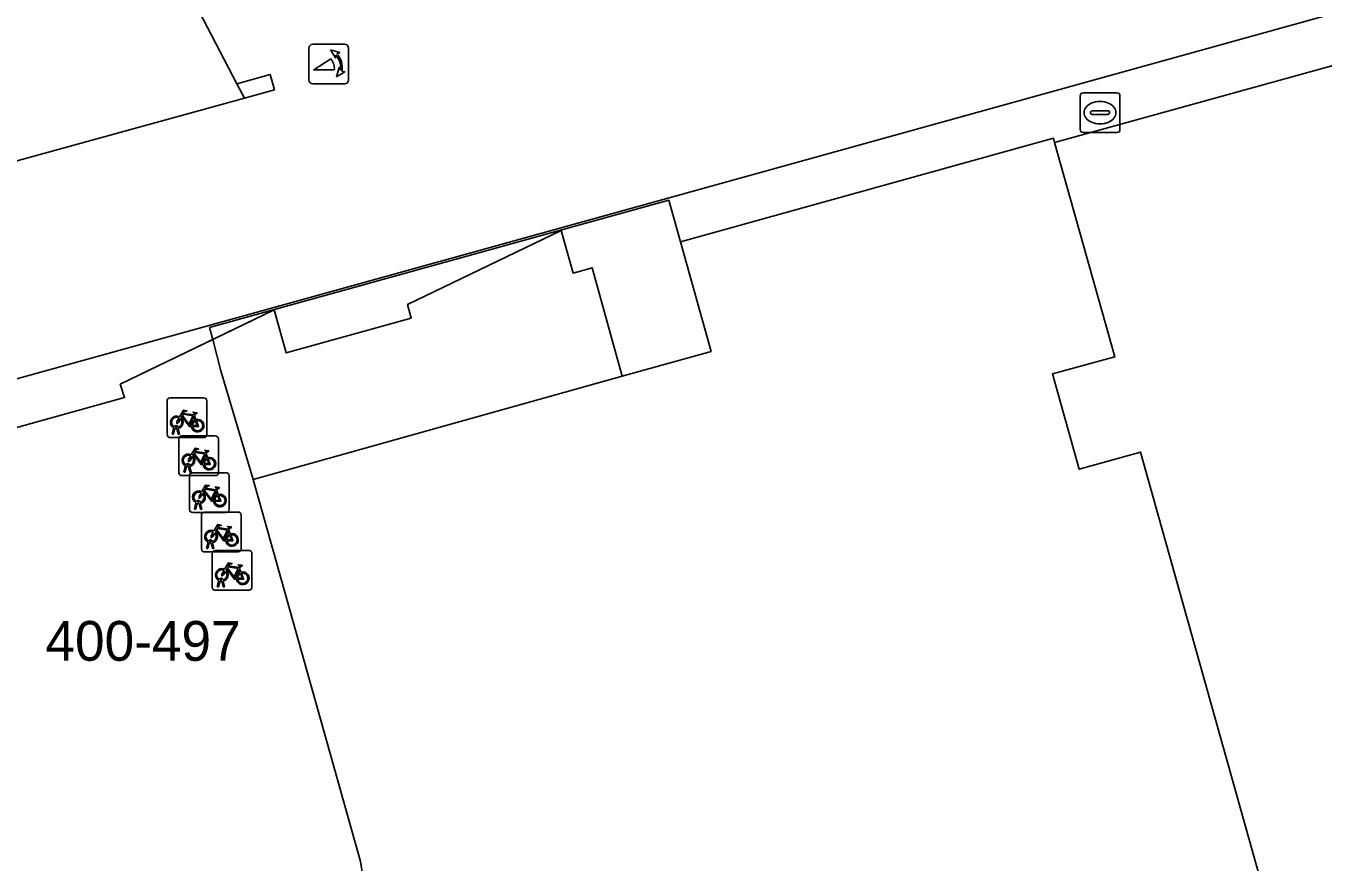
# Model space of a CAD drawing. Extents: x 159053 to 160042, y 380449 to 381423.
# Drawn here: x 159209.05 to 159241.67, y 381114.07 to 381135.09 of the extents above; entities that cross this region are included whole.
import ezdxf

# ---------------------------------------------------------------- set-up
doc = ezdxf.new("R2010")
doc.units = 0
for name, color, linetype in [('IMGEO_Fietsenrek', 7, 'Continuous'), ('IMGEO_Groenvoorziening', 7, 'Continuous'), ('IMGEO_Kolk', 7, 'Continuous'), ('IMGEO_Muur', 7, 'Continuous'), ('IMGEO_Pand', 7, 'Continuous'), ('IMGEO_Pand_nummerreeks', 7, 'Continuous'), ('IMGEO_Pand_overbouw', 7, 'Continuous'), ('IMGEO_Pand_vergunning_verleend', 7, 'Continuous'), ('IMGEO_Poller', 7, 'Continuous'), ('IMGEO_Rijbaan_lokaal_open', 7, 'Continuous'), ('IMGEO_Voetpad_open', 7, 'Continuous')]:
    doc.layers.add(name, color=color, linetype=linetype)

msp = doc.modelspace()

# ---------------------------------------------------------------- linework, layer by layer
at = {"layer": 'IMGEO_Fietsenrek'}
for p, q in [((159212.605, 381124.816), (159212.605, 381125.657)), ((159212.605, 381125.657), (159212.605, 381124.816)), ((159212.68, 381125.741), (159213.521, 381125.741)), ((159213.521, 381125.741), (159212.68, 381125.741)), ((159213.605, 381125.666), (159213.605, 381124.825)), ((159213.605, 381124.825), (159213.605, 381125.666)), ((159213.292, 381125.29), (159213.328, 381125.195)), ((159212.732, 381124.825), (159212.771, 381124.985)), ((159212.801, 381124.973), (159212.766, 381124.825)), ((159212.843, 381124.997), (159212.842, 381125.001)), ((159212.884, 381124.825), (159212.85, 381124.967)), ((159212.874, 381125.008), (159212.875, 381125.001)), ((159212.882, 381124.971), (159212.917, 381124.825)), ((159213.53, 381124.741), (159212.689, 381124.741)), ((159212.689, 381124.741), (159213.53, 381124.741)), ((159212.766, 381124.825), (159212.732, 381124.825)), ((159212.917, 381124.825), (159212.884, 381124.825)), ((159212.899, 381123.86), (159212.899, 381124.701)), ((159212.899, 381124.701), (159212.899, 381123.86)), ((159212.974, 381124.785), (159213.815, 381124.785)), ((159213.815, 381124.785), (159212.974, 381124.785)), ((159213.899, 381124.71), (159213.899, 381123.869)), ((159213.899, 381123.869), (159213.899, 381124.71)), ((159213.586, 381124.334), (159213.622, 381124.239)), ((159213.026, 381123.869), (159213.065, 381124.029)), ((159213.095, 381124.017), (159213.06, 381123.869)), ((159213.137, 381124.041), (159213.136, 381124.045)), ((159213.178, 381123.869), (159213.144, 381124.011)), ((159213.168, 381124.052), (159213.169, 381124.045)), ((159213.176, 381124.015), (159213.211, 381123.869)), ((159213.824, 381123.785), (159212.983, 381123.785)), ((159212.983, 381123.785), (159213.824, 381123.785)), ((159213.06, 381123.869), (159213.026, 381123.869)), ((159213.164, 381122.934), (159213.164, 381123.775)), ((159213.164, 381123.775), (159213.164, 381122.934)), ((159213.211, 381123.869), (159213.178, 381123.869)), ((159213.239, 381123.859), (159214.08, 381123.859)), ((159214.08, 381123.859), (159213.239, 381123.859)), ((159214.164, 381123.784), (159214.164, 381122.943)), ((159214.164, 381122.943), (159214.164, 381123.784)), ((159213.851, 381123.408), (159213.887, 381123.313)), ((159213.291, 381122.943), (159213.33, 381123.103)), ((159213.36, 381123.091), (159213.325, 381122.943)), ((159213.402, 381123.115), (159213.401, 381123.119)), ((159213.443, 381122.943), (159213.409, 381123.085)), ((159213.433, 381123.126), (159213.434, 381123.119)), ((159213.441, 381123.089), (159213.476, 381122.943)), ((159214.089, 381122.859), (159213.248, 381122.859)), ((159213.248, 381122.859), (159214.089, 381122.859)), ((159213.325, 381122.943), (159213.291, 381122.943)), ((159213.476, 381122.943), (159213.443, 381122.943)), ((159213.468, 381121.943), (159213.468, 381122.784)), ((159213.468, 381122.784), (159213.468, 381121.943)), ((159213.543, 381122.868), (159214.384, 381122.868)), ((159214.384, 381122.868), (159213.543, 381122.868)), ((159214.468, 381122.793), (159214.468, 381121.952)), ((159214.468, 381121.952), (159214.468, 381122.793)), ((159214.155, 381122.417), (159214.191, 381122.322)), ((159213.595, 381121.952), (159213.634, 381122.112)), ((159213.664, 381122.1), (159213.629, 381121.952)), ((159213.706, 381122.124), (159213.705, 381122.128)), ((159213.747, 381121.952), (159213.713, 381122.094)), ((159213.737, 381122.135), (159213.738, 381122.128)), ((159213.745, 381122.098), (159213.78, 381121.952)), ((159214.393, 381121.868), (159213.552, 381121.868)), ((159213.552, 381121.868), (159214.393, 381121.868)), ((159213.629, 381121.952), (159213.595, 381121.952)), ((159213.738, 381120.98), (159213.738, 381121.821)), ((159213.738, 381121.821), (159213.738, 381120.98)), ((159213.78, 381121.952), (159213.747, 381121.952)), ((159213.813, 381121.905), (159214.654, 381121.905)), ((159214.654, 381121.905), (159213.813, 381121.905)), ((159214.738, 381121.83), (159214.738, 381120.989)), ((159214.738, 381120.989), (159214.738, 381121.83)), ((159214.425, 381121.454), (159214.461, 381121.359)), ((159213.865, 381120.989), (159213.904, 381121.149)), ((159213.934, 381121.137), (159213.899, 381120.989)), ((159213.976, 381121.161), (159213.975, 381121.165)), ((159214.017, 381120.989), (159213.983, 381121.131)), ((159214.007, 381121.172), (159214.008, 381121.165)), ((159214.015, 381121.135), (159214.05, 381120.989)), ((159214.663, 381120.905), (159213.822, 381120.905)), ((159213.822, 381120.905), (159214.663, 381120.905)), ((159213.899, 381120.989), (159213.865, 381120.989)), ((159214.05, 381120.989), (159214.017, 381120.989))]:
    msp.add_line(p, q, dxfattribs=at)
for points in [[(159212.918, 381125.267), (159213.013, 381125.431), (159213.099, 381125.417), (159213.101, 381125.408), (159213.045, 381125.397), (159213.018, 381125.352), (159213.274, 381125.311)], [(159213.261, 381125.286), (159213.004, 381125.327), (159212.987, 381125.298), (159213.154, 381125.078), (159213.261, 381125.286)], [(159213.274, 381125.311), (159213.299, 381125.36), (159213.293, 381125.364), (159213.27, 381125.368), (159213.258, 381125.375), (159213.257, 381125.378), (159213.259, 381125.383), (159213.354, 381125.368), (159213.356, 381125.358), (159213.346, 381125.345), (159213.334, 381125.339), (159213.32, 381125.345), (159213.292, 381125.29)], [(159212.939, 381125.215), (159212.887, 381125.125), (159212.847, 381125.1), (159212.848, 381125.147), (159212.903, 381125.241)], [(159213.214, 381125.023), (159213.164, 381125.023), (159212.973, 381125.274), (159212.954, 381125.242)], [(159213.309, 381125.188), (159213.279, 381125.265), (159213.17, 381125.047), (159213.213, 381125.047)], [(159213.243, 381125.047), (159213.363, 381125.046), (159213.319, 381125.16)], [(159213.339, 381125.167), (159213.394, 381125.022), (159213.244, 381125.022)], [(159213.212, 381124.311), (159213.307, 381124.475), (159213.393, 381124.461), (159213.395, 381124.452), (159213.339, 381124.441), (159213.312, 381124.396), (159213.568, 381124.355)], [(159213.508, 381124.067), (159213.458, 381124.067), (159213.267, 381124.318), (159213.248, 381124.286)], [(159213.555, 381124.33), (159213.298, 381124.371), (159213.281, 381124.342), (159213.448, 381124.122), (159213.555, 381124.33)], [(159213.603, 381124.232), (159213.573, 381124.309), (159213.464, 381124.091), (159213.507, 381124.091)], [(159213.568, 381124.355), (159213.593, 381124.404), (159213.587, 381124.408), (159213.564, 381124.412), (159213.552, 381124.419), (159213.551, 381124.422), (159213.553, 381124.427), (159213.648, 381124.412), (159213.65, 381124.402), (159213.64, 381124.389), (159213.628, 381124.383), (159213.614, 381124.389), (159213.586, 381124.334)], [(159213.233, 381124.259), (159213.181, 381124.169), (159213.141, 381124.144), (159213.142, 381124.191), (159213.197, 381124.285)], [(159213.537, 381124.091), (159213.657, 381124.09), (159213.613, 381124.204)], [(159213.633, 381124.211), (159213.688, 381124.066), (159213.538, 381124.066)], [(159213.498, 381123.333), (159213.446, 381123.243), (159213.406, 381123.218), (159213.407, 381123.265), (159213.462, 381123.359)], [(159213.477, 381123.385), (159213.572, 381123.549), (159213.658, 381123.535), (159213.66, 381123.526), (159213.604, 381123.515), (159213.577, 381123.47), (159213.833, 381123.429)], [(159213.773, 381123.141), (159213.723, 381123.141), (159213.532, 381123.392), (159213.513, 381123.36)], [(159213.82, 381123.404), (159213.563, 381123.445), (159213.546, 381123.416), (159213.713, 381123.196), (159213.82, 381123.404)], [(159213.868, 381123.306), (159213.838, 381123.383), (159213.729, 381123.165), (159213.772, 381123.165)], [(159213.833, 381123.429), (159213.858, 381123.478), (159213.852, 381123.482), (159213.829, 381123.486), (159213.817, 381123.493), (159213.816, 381123.496), (159213.818, 381123.501), (159213.913, 381123.486), (159213.915, 381123.476), (159213.905, 381123.463), (159213.893, 381123.457), (159213.879, 381123.463), (159213.851, 381123.408)], [(159213.802, 381123.165), (159213.922, 381123.164), (159213.878, 381123.278)], [(159213.898, 381123.285), (159213.953, 381123.14), (159213.803, 381123.14)], [(159213.802, 381122.342), (159213.75, 381122.252), (159213.71, 381122.227), (159213.711, 381122.274), (159213.766, 381122.368)], [(159213.781, 381122.394), (159213.876, 381122.558), (159213.962, 381122.544), (159213.964, 381122.535), (159213.908, 381122.524), (159213.881, 381122.479), (159214.137, 381122.438)], [(159214.077, 381122.15), (159214.027, 381122.15), (159213.836, 381122.401), (159213.817, 381122.369)], [(159214.124, 381122.413), (159213.867, 381122.454), (159213.85, 381122.425), (159214.017, 381122.205), (159214.124, 381122.413)], [(159214.172, 381122.315), (159214.142, 381122.392), (159214.033, 381122.174), (159214.076, 381122.174)], [(159214.137, 381122.438), (159214.162, 381122.487), (159214.156, 381122.491), (159214.133, 381122.495), (159214.121, 381122.502), (159214.12, 381122.505), (159214.122, 381122.51), (159214.217, 381122.495), (159214.219, 381122.485), (159214.209, 381122.472), (159214.197, 381122.466), (159214.183, 381122.472), (159214.155, 381122.417)], [(159214.106, 381122.174), (159214.226, 381122.173), (159214.182, 381122.287)], [(159214.202, 381122.294), (159214.257, 381122.149), (159214.107, 381122.149)], [(159214.072, 381121.379), (159214.02, 381121.289), (159213.98, 381121.264), (159213.981, 381121.311), (159214.036, 381121.405)], [(159214.051, 381121.431), (159214.146, 381121.595), (159214.232, 381121.581), (159214.234, 381121.572), (159214.178, 381121.561), (159214.151, 381121.516), (159214.407, 381121.475)], [(159214.347, 381121.187), (159214.297, 381121.187), (159214.106, 381121.438), (159214.087, 381121.406)], [(159214.394, 381121.45), (159214.137, 381121.491), (159214.12, 381121.462), (159214.287, 381121.242), (159214.394, 381121.45)], [(159214.442, 381121.352), (159214.412, 381121.429), (159214.303, 381121.211), (159214.346, 381121.211)], [(159214.407, 381121.475), (159214.432, 381121.524), (159214.426, 381121.528), (159214.403, 381121.532), (159214.391, 381121.539), (159214.39, 381121.542), (159214.392, 381121.547), (159214.487, 381121.532), (159214.489, 381121.522), (159214.479, 381121.509), (159214.467, 381121.503), (159214.453, 381121.509), (159214.425, 381121.454)], [(159214.376, 381121.211), (159214.496, 381121.21), (159214.452, 381121.324)], [(159214.472, 381121.331), (159214.527, 381121.186), (159214.377, 381121.186)]]:
    msp.add_lwpolyline(points, dxfattribs=at)
for centre, radius, start, end in [((159212.683, 381125.663), 0.0779, 92.4484, 184.2845), ((159212.683, 381125.663), 0.0779, 92.4484, 184.2845), ((159213.527, 381125.663), 0.0779, 2.4484, 94.2845), ((159213.527, 381125.663), 0.0779, 2.4484, 94.2845), ((159212.845, 381125.126), 0.159, 62.6766, 242.1369), ((159212.845, 381125.126), 0.129, 63.3192, 238.903), ((159212.825, 381124.997), 0.0499, 12.8025, 158.6934), ((159212.845, 381125.126), 0.159, 253.9967, 271.7867), ((159212.825, 381124.997), 0.0174, 12.8025, 163.4502), ((159212.845, 381125.126), 0.129, 253.415, 269.0204), ((159212.845, 381125.126), 0.129, 283.6043, 43.4302), ((159212.845, 381125.126), 0.159, 283.5766, 46.6042), ((159213.372, 381125.042), 0.159, 113.3408, 178.3217), ((159213.372, 381125.042), 0.159, 187.0065, 105.7708), ((159213.372, 381125.042), 0.129, 113.923, 177.9556), ((159213.372, 381125.042), 0.129, 188.6715, 104.5883), ((159212.683, 381124.819), 0.0779, 182.4484, 274.2845), ((159212.683, 381124.819), 0.0779, 182.4484, 274.2845), ((159212.977, 381124.707), 0.0779, 92.4484, 184.2845), ((159212.977, 381124.707), 0.0779, 92.4484, 184.2845), ((159213.527, 381124.819), 0.0779, 272.4484, 4.2845), ((159213.527, 381124.819), 0.0779, 272.4484, 4.2845), ((159213.821, 381124.707), 0.0779, 2.4484, 94.2845), ((159213.821, 381124.707), 0.0779, 2.4484, 94.2845), ((159213.139, 381124.17), 0.159, 62.6766, 242.1369), ((159213.139, 381124.17), 0.129, 63.3192, 238.903), ((159213.119, 381124.041), 0.0499, 12.8025, 158.6934), ((159213.139, 381124.17), 0.159, 253.9967, 271.7867), ((159213.119, 381124.041), 0.0174, 12.8025, 163.4502), ((159213.139, 381124.17), 0.129, 253.415, 269.0204), ((159213.139, 381124.17), 0.129, 283.6043, 43.4302), ((159213.139, 381124.17), 0.159, 283.5766, 46.6042), ((159213.666, 381124.086), 0.159, 113.3408, 178.3217), ((159213.666, 381124.086), 0.159, 187.0065, 105.7708), ((159213.666, 381124.086), 0.129, 113.923, 177.9556), ((159213.666, 381124.086), 0.129, 188.6715, 104.5883), ((159212.977, 381123.863), 0.0779, 182.4484, 274.2845), ((159212.977, 381123.863), 0.0779, 182.4484, 274.2845), ((159213.242, 381123.781), 0.0779, 92.4484, 184.2845), ((159213.242, 381123.781), 0.0779, 92.4484, 184.2845), ((159213.821, 381123.863), 0.0779, 272.4484, 4.2845), ((159213.821, 381123.863), 0.0779, 272.4484, 4.2845), ((159214.086, 381123.781), 0.0779, 2.4484, 94.2845), ((159214.086, 381123.781), 0.0779, 2.4484, 94.2845), ((159213.404, 381123.244), 0.159, 62.6766, 242.1369), ((159213.404, 381123.244), 0.129, 63.3192, 238.903), ((159213.404, 381123.244), 0.129, 283.6043, 43.4302), ((159213.404, 381123.244), 0.159, 283.5766, 46.6042), ((159213.384, 381123.115), 0.0499, 12.8025, 158.6934), ((159213.404, 381123.244), 0.159, 253.9967, 271.7867), ((159213.384, 381123.115), 0.0174, 12.8025, 163.4502), ((159213.404, 381123.244), 0.129, 253.415, 269.0204), ((159213.931, 381123.16), 0.159, 113.3408, 178.3217), ((159213.931, 381123.16), 0.159, 187.0065, 105.7708), ((159213.931, 381123.16), 0.129, 113.923, 177.9556), ((159213.931, 381123.16), 0.129, 188.6715, 104.5883), ((159213.242, 381122.937), 0.0779, 182.4484, 274.2845), ((159213.242, 381122.937), 0.0779, 182.4484, 274.2845), ((159213.546, 381122.79), 0.0779, 92.4484, 184.2845), ((159213.546, 381122.79), 0.0779, 92.4484, 184.2845), ((159214.086, 381122.937), 0.0779, 272.4484, 4.2845), ((159214.086, 381122.937), 0.0779, 272.4484, 4.2845), ((159214.39, 381122.79), 0.0779, 2.4484, 94.2845), ((159214.39, 381122.79), 0.0779, 2.4484, 94.2845), ((159213.708, 381122.253), 0.159, 62.6766, 242.1369), ((159213.708, 381122.253), 0.129, 63.3192, 238.903), ((159213.708, 381122.253), 0.129, 283.6043, 43.4302), ((159213.708, 381122.253), 0.159, 283.5766, 46.6042), ((159213.688, 381122.124), 0.0499, 12.8025, 158.6934), ((159213.708, 381122.253), 0.159, 253.9967, 271.7867), ((159213.688, 381122.124), 0.0174, 12.8025, 163.4502), ((159213.708, 381122.253), 0.129, 253.415, 269.0204), ((159214.235, 381122.169), 0.159, 113.3408, 178.3217), ((159214.235, 381122.169), 0.159, 187.0065, 105.7708), ((159214.235, 381122.169), 0.129, 113.923, 177.9556), ((159214.235, 381122.169), 0.129, 188.6715, 104.5883), ((159213.546, 381121.946), 0.0779, 182.4484, 274.2845), ((159213.546, 381121.946), 0.0779, 182.4484, 274.2845), ((159213.816, 381121.827), 0.0779, 92.4484, 184.2845), ((159213.816, 381121.827), 0.0779, 92.4484, 184.2845), ((159214.39, 381121.946), 0.0779, 272.4484, 4.2845), ((159214.39, 381121.946), 0.0779, 272.4484, 4.2845), ((159214.66, 381121.827), 0.0779, 2.4484, 94.2845), ((159214.66, 381121.827), 0.0779, 2.4484, 94.2845), ((159213.978, 381121.29), 0.159, 62.6766, 242.1369), ((159213.978, 381121.29), 0.129, 63.3192, 238.903), ((159213.978, 381121.29), 0.129, 283.6043, 43.4302), ((159213.978, 381121.29), 0.159, 283.5766, 46.6042), ((159214.505, 381121.206), 0.159, 187.0065, 105.7708), ((159213.958, 381121.161), 0.0499, 12.8025, 158.6934), ((159213.978, 381121.29), 0.159, 253.9967, 271.7867), ((159213.958, 381121.161), 0.0174, 12.8025, 163.4502), ((159213.978, 381121.29), 0.129, 253.415, 269.0204), ((159214.505, 381121.206), 0.159, 113.3408, 178.3217), ((159214.505, 381121.206), 0.129, 113.923, 177.9556), ((159214.505, 381121.206), 0.129, 188.6715, 104.5883), ((159213.816, 381120.983), 0.0779, 182.4484, 274.2845), ((159213.816, 381120.983), 0.0779, 182.4484, 274.2845), ((159214.66, 381120.983), 0.0779, 272.4484, 4.2845), ((159214.66, 381120.983), 0.0779, 272.4484, 4.2845)]:
    msp.add_arc(centre, radius, start, end, dxfattribs=at)
at = {"layer": 'IMGEO_Groenvoorziening'}
msp.add_lwpolyline([(159203.863, 381153.784), (159203.675, 381154.146), (159191.253, 381150.756), (159191.792, 381148.906), (159190.735, 381148.635), (159194.74, 381138.894), (159197.157, 381139.769), (159201.066, 381129.977), (159201.215, 381129.603), (159214.549, 381133.275), (159214.36, 381133.638)], close=True, dxfattribs=at)
msp.add_lwpolyline([(159250.944, 381109.911), (159244.137, 381134.711), (159234.919, 381132.158), (159236.433, 381126.772), (159234.862, 381126.343), (159235.536, 381123.945), (159237.076, 381124.378), (159240.451, 381112.37)], dxfattribs=at)
at = {"layer": 'IMGEO_Kolk'}
for p, q in [((159235.559, 381132.485), (159235.559, 381133.337)), ((159235.634, 381133.411), (159236.486, 381133.411)), ((159236.047, 381133.191), (159236.072, 381133.191)), ((159236.56, 381133.337), (159236.56, 381132.485)), ((159235.818, 381132.905), (159235.818, 381132.917)), ((159236.256, 381132.868), (159235.858, 381132.868)), ((159235.861, 381132.954), (159236.259, 381132.954)), ((159236.302, 381132.917), (159236.302, 381132.905)), ((159236.07, 381132.631), (159236.045, 381132.631)), ((159236.486, 381132.411), (159235.634, 381132.411))]:
    msp.add_line(p, q, dxfattribs=at)
for points in [[(159235.559, 381132.485), (159235.559, 381133.337)], [(159235.634, 381133.411), (159236.486, 381133.411)], [(159236.56, 381133.337), (159236.56, 381132.485)], [(159236.486, 381132.411), (159235.634, 381132.411)]]:
    msp.add_lwpolyline(points, dxfattribs=at)
for centre, radius, start, end in [((159235.636, 381133.335), 0.0765, 91.552, 178.448), ((159235.636, 381133.335), 0.0765, 91.552, 178.448), ((159236.484, 381133.335), 0.0765, 1.552, 88.448), ((159236.484, 381133.335), 0.0765, 1.552, 88.448), ((159235.858, 381132.914), 0.0403, 85.8775, 175.7526), ((159235.855, 381132.904), 0.0366, 178.938, 274.7102), ((159236.259, 381132.911), 0.043, 264.8664, 352.4533), ((159236.263, 381132.916), 0.0386, 1.7309, 96.639), ((159235.636, 381132.487), 0.0765, 181.552, 268.448), ((159235.636, 381132.487), 0.0765, 181.552, 268.448), ((159236.484, 381132.487), 0.0765, 271.552, 358.448), ((159236.484, 381132.487), 0.0765, 271.552, 358.448)]:
    msp.add_arc(centre, radius, start, end, dxfattribs=at)
for centre, major_axis, ratio, start_param, end_param in [((159236.046, 381132.911), (-0.387, 0.002), 0.722429, 4.712389, 7.853982), ((159236.071, 381132.911), (-0.39, 0.002), 0.717154, 1.570796, 4.712389)]:
    msp.add_ellipse(centre, major_axis=major_axis, ratio=ratio, start_param=start_param, end_param=end_param, dxfattribs=at)
at = {"layer": 'IMGEO_Muur'}
msp.add_lwpolyline([(159214.549, 381133.275), (159215.304, 381133.483), (159215.198, 381133.869), (159214.36, 381133.638)], close=True, dxfattribs=at)
at = {"layer": 'IMGEO_Pand'}
msp.add_lwpolyline([(159240.451, 381112.37), (159237.076, 381124.378), (159235.536, 381123.945), (159234.862, 381126.343), (159236.433, 381126.772), (159234.919, 381132.158), (159234.888, 381132.268), (159225.516, 381129.666), (159226.281, 381126.91), (159224.046, 381126.285), (159214.766, 381123.688), (159217.466, 381114.086), (159217.839, 381111.782)], dxfattribs=at)
at = {"layer": 'IMGEO_Pand_overbouw'}
msp.add_lwpolyline([(159249.617, 381146.417), (159253.067, 381147.375), (159252.059, 381151.007), (159248.609, 381150.05), (159244.524, 381164.774), (159216.821, 381157.087), (159215.484, 381161.905), (159146.712, 381142.823), (159144.149, 381142.112), (159127.074, 381137.375), (159127.322, 381136.481), (159127.96, 381134.183), (159128.847, 381130.986), (159129.855, 381127.353), (159132.702, 381117.091), (159133.413, 381114.528), (159135.79, 381105.961), (159251.903, 381138.179)], close=True, dxfattribs=at)
msp.add_lwpolyline([(159217.839, 381111.782), (159217.466, 381114.086), (159214.766, 381123.688), (159224.046, 381126.285), (159223.287, 381129.01), (159222.813, 381128.878), (159222.515, 381129.95), (159218.651, 381128.089), (159218.739, 381127.747), (159215.597, 381126.875), (159215.296, 381127.954), (159211.427, 381126.085), (159211.535, 381125.747), (159208.368, 381124.868)], dxfattribs=at)
at = {"layer": 'IMGEO_Pand_vergunning_verleend'}
msp.add_lwpolyline([(159251.903, 381138.179), (159135.79, 381105.961), (159133.413, 381114.528), (159130.137, 381113.619), (159129.426, 381116.182), (159132.702, 381117.091), (159129.855, 381127.353), (159126.405, 381126.396), (159125.397, 381130.029), (159128.847, 381130.986), (159127.074, 381137.375), (159144.149, 381142.112), (159143.24, 381145.388), (159145.803, 381146.1), (159146.712, 381142.823), (159215.484, 381161.905), (159216.821, 381157.087), (159244.524, 381164.774), (159248.609, 381150.05), (159252.059, 381151.007), (159253.067, 381147.375), (159249.617, 381146.417)], close=True, dxfattribs=at)
at = {"layer": 'IMGEO_Poller'}
for p, q in [((159216.17, 381134.535), (159216.17, 381133.728)), ((159216.17, 381134.535), (159216.17, 381133.728)), ((159217.072, 381134.63), (159216.264, 381134.63)), ((159217.072, 381134.63), (159216.264, 381134.63)), ((159217.166, 381133.728), (159217.166, 381134.535)), ((159217.166, 381133.728), (159217.166, 381134.535)), ((159216.264, 381133.633), (159217.072, 381133.633)), ((159216.264, 381133.633), (159217.072, 381133.633))]:
    msp.add_line(p, q, dxfattribs=at)
for points in [[(159216.849, 381134.359), (159216.837, 381134.286), (159216.712, 381134.491)], [(159216.712, 381134.491), (159216.943, 381134.425), (159216.872, 381134.393)], [(159216.805, 381133.986), (159216.292, 381133.986), (159216.722, 381134.261)], [(159216.865, 381133.814), (159216.931, 381134.045), (159216.961, 381133.977)], [(159216.997, 381133.95), (159217.069, 381133.939), (159216.865, 381133.814)]]:
    msp.add_lwpolyline(points, dxfattribs=at)
for centre, radius, start, end in [((159216.264, 381134.535), 0.0946, 90, 180), ((159216.264, 381134.535), 0.0946, 90, 180), ((159217.072, 381134.535), 0.0946, 0, 90), ((159217.072, 381134.535), 0.0946, 0, 90), ((159216.477, 381134.036), 0.332, 351.3247, 42.4854), ((159216.491, 381134.046), 0.476, 351.7527, 41.1691), ((159216.491, 381134.046), 0.516, 349.3569, 42.2912), ((159216.264, 381133.728), 0.0946, 180, 270), ((159216.264, 381133.728), 0.0946, 180, 270), ((159217.072, 381133.728), 0.0946, 270, 0), ((159217.072, 381133.728), 0.0946, 270, 0)]:
    msp.add_arc(centre, radius, start, end, dxfattribs=at)
at = {"layer": 'IMGEO_Rijbaan_lokaal_open'}
msp.add_lwpolyline([(159214.36, 381133.638), (159215.198, 381133.869), (159215.304, 381133.483), (159214.549, 381133.275), (159201.215, 381129.603), (159197.876, 381128.684), (159197.77, 381129.069), (159201.066, 381129.977), (159197.157, 381139.769), (159194.74, 381138.894), (159190.735, 381148.635), (159191.792, 381148.906), (159191.253, 381150.756), (159203.675, 381154.146), (159205.196, 381154.568), (159205.303, 381154.186), (159203.863, 381153.784)], close=True, dxfattribs=at)
msp.add_lwpolyline([(159188.753, 381119.422), (159189.794, 381119.711), (159189.69, 381120.073), (159193.569, 381121.905), (159193.908, 381120.853), (159197.06, 381121.728), (159196.94, 381122.081), (159200.811, 381123.919), (159201.133, 381122.859), (159204.289, 381123.735), (159204.184, 381124.071), (159208.069, 381125.935), (159208.368, 381124.868), (159211.535, 381125.747), (159211.427, 381126.085), (159213.75, 381127.207), (159213.672, 381127.507), (159225.215, 381130.711), (159225.516, 381129.666), (159234.888, 381132.268), (159234.919, 381132.158), (159244.137, 381134.711)], dxfattribs=at)
at = {"layer": 'IMGEO_Voetpad_open'}
for points in [[(159225.516, 381129.666), (159225.215, 381130.711), (159213.672, 381127.507), (159213.75, 381127.207), (159215.296, 381127.954), (159215.597, 381126.875), (159218.739, 381127.747), (159218.651, 381128.089), (159222.515, 381129.95), (159222.813, 381128.878), (159223.287, 381129.01), (159224.046, 381126.285), (159226.281, 381126.91)], [(159224.046, 381126.285), (159223.287, 381129.01), (159222.813, 381128.878), (159222.515, 381129.95), (159218.651, 381128.089), (159218.739, 381127.747), (159215.597, 381126.875), (159215.296, 381127.954), (159213.75, 381127.207), (159213.952, 381126.418), (159214.766, 381123.688)]]:
    msp.add_lwpolyline(points, close=True, dxfattribs=at)
msp.add_lwpolyline([(159217.839, 381111.782), (159217.466, 381114.086), (159214.766, 381123.688), (159213.952, 381126.418), (159213.75, 381127.207), (159211.427, 381126.085), (159211.535, 381125.747), (159208.368, 381124.868), (159208.069, 381125.935), (159204.184, 381124.071), (159204.289, 381123.735), (159201.133, 381122.859), (159200.811, 381123.919), (159196.94, 381122.081), (159197.06, 381121.728), (159193.908, 381120.853), (159193.569, 381121.905), (159189.69, 381120.073), (159189.794, 381119.711), (159188.753, 381119.422)], dxfattribs=at)

# ---------------------------------------------------------------- texts
at = {"layer": 'IMGEO_Pand_nummerreeks'}
msp.add_text('400-497', height=1, dxfattribs=at).set_placement((159209.545, 381119.131))

doc.saveas('drawing.dxf')
